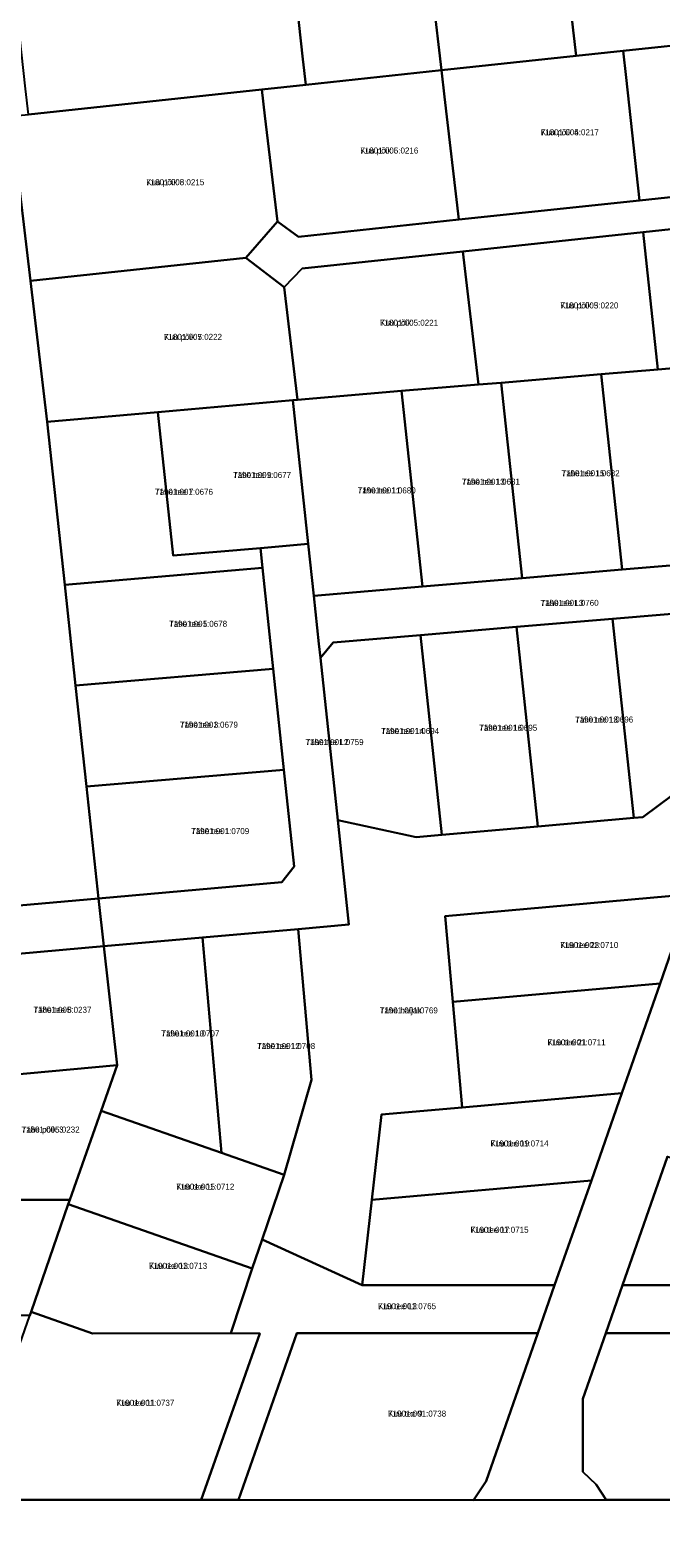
# Model space of a CAD drawing. Extents: x 529768 to 552006, y 6562269 to 6580975.
# Drawn here: x 536990.2 to 537147.7, y 6574791.4 to 6575167.4 of the extents above; entities that cross this region are included whole.
import ezdxf

# ---------------------------------------------------------------- set-up
doc = ezdxf.new("R2010")
doc.units = 0
for name, color, linetype in [('L_AADRESS', 7, 'Continuous'), ('PIIR', 7, 'Continuous'), ('TUNNUS', 7, 'Continuous')]:
    doc.layers.add(name, color=color, linetype=linetype)

msp = doc.modelspace()

# ---------------------------------------------------------------- linework, layer by layer
at = {"layer": 'PIIR'}
for points in [[(537087.57, 6575203.86), (537092.16, 6575163.84), (537092.9, 6575157.43), (537059.07, 6575153.83), (537058.36, 6575160.23), (537054.88, 6575191.53), (537061.85, 6575201.29)], [(537121.39, 6575207.24), (537122.33, 6575198.78), (537125.81, 6575167.42), (537126.53, 6575161.02), (537092.9, 6575157.43), (537092.16, 6575163.84), (537087.57, 6575203.86)], [(537122.33, 6575198.78), (537178.02, 6575204.73), (537181.66, 6575173.37), (537182.4, 6575166.98), (537138.33, 6575162.28), (537126.53, 6575161.02), (537125.81, 6575167.42)], [(536984.76, 6575192.53), (537045.52, 6575199.03), (537054.88, 6575191.53), (537058.36, 6575160.23), (537059.07, 6575153.83), (537048.08, 6575152.65), (536989.8, 6575146.44), (536989.09, 6575152.84)], [(537044.13, 6575110.65), (537051.97, 6575119.73), (537057.24, 6575115.92), (537097.3, 6575120.19), (537142.39, 6575125), (537182.73, 6575129.3), (537181.58, 6575139.24), (537185.56, 6575139.66), (537183.16, 6575160.38), (537182.4, 6575166.98), (537184.57, 6575167.21), (537193.32, 6575086.82), (537191.69, 6575086.66), (537187.63, 6575121.78), (537143.25, 6575117.05), (537098.24, 6575112.24), (537058.16, 6575107.97), (537053.62, 6575103.32)], [(537138.33, 6575162.28), (537182.4, 6575166.98), (537183.16, 6575160.38), (537185.56, 6575139.66), (537181.58, 6575139.24), (537182.73, 6575129.3), (537142.39, 6575125), (537139.05, 6575155.67)], [(537092.9, 6575157.43), (537126.53, 6575161.02), (537138.33, 6575162.28), (537139.05, 6575155.67), (537142.39, 6575125), (537097.3, 6575120.19), (537093.68, 6575150.83)], [(537048.08, 6575152.65), (537059.07, 6575153.83), (537092.9, 6575157.43), (537093.68, 6575150.83), (537097.3, 6575120.19), (537057.24, 6575115.92), (537051.97, 6575119.73), (537048.86, 6575146.05)], [(536985.5, 6575145.98), (536989.8, 6575146.44), (537048.08, 6575152.65), (537048.86, 6575146.05), (537051.97, 6575119.73), (537044.13, 6575110.65), (536990.35, 6575104.91), (536986.28, 6575139.38)], [(537007.29, 6574950.89), (536901.57, 6574941.52), (536880.9, 6575127.58), (536880.17, 6575134.18), (536908, 6575137.3), (536935.42, 6575140.37), (536985.5, 6575145.98), (536986.28, 6575139.38), (536990.35, 6575104.91), (536994.51, 6575069.75), (536998.88, 6575029.1), (537001.6, 6575003.96), (537004.29, 6574978.77)], [(537146.93, 6575082.84), (537143.25, 6575117.05), (537187.63, 6575121.78), (537191.69, 6575086.66), (537157.72, 6575083.76)], [(537107.8, 6575079.49), (537102.14, 6575079.04), (537098.24, 6575112.24), (537143.25, 6575117.05), (537146.93, 6575082.84), (537132.83, 6575081.61)], [(537022.12, 6575072.17), (536994.51, 6575069.75), (536990.35, 6575104.91), (537044.13, 6575110.65), (537053.62, 6575103.32), (537057.02, 6575075.25), (537055.85, 6575075.14)], [(537057.02, 6575075.25), (537053.62, 6575103.32), (537058.16, 6575107.97), (537098.24, 6575112.24), (537102.14, 6575079.04), (537082.94, 6575077.45)], [(537138.02, 6575032.9), (537132.83, 6575081.61), (537146.93, 6575082.84), (537157.72, 6575083.76), (537162.92, 6575034.97)], [(537113.11, 6575030.76), (537107.8, 6575079.49), (537132.83, 6575081.61), (537138.02, 6575032.9)], [(537059.69, 6575039.29), (537055.85, 6575075.14), (537057.02, 6575075.25), (537082.94, 6575077.45), (537088.17, 6575028.66), (537061.07, 6575026.35)], [(537088.17, 6575028.66), (537082.94, 6575077.45), (537102.14, 6575079.04), (537107.8, 6575079.49), (537113.11, 6575030.76)], [(536998.88, 6575029.1), (536994.51, 6575069.75), (537022.12, 6575072.17), (537025.91, 6575036.43), (537047.73, 6575038.27), (537048.27, 6575033.31)], [(537025.91, 6575036.43), (537022.12, 6575072.17), (537055.85, 6575075.14), (537059.69, 6575039.29), (537047.73, 6575038.27)], [(537048.27, 6575033.31), (537047.73, 6575038.27), (537059.69, 6575039.29), (537061.07, 6575026.35), (537062.34, 6575014.42), (537062.7, 6575010.87), (537067.05, 6574970.39), (537069.8, 6574944.41), (537057.19, 6574943.22), (537033.27, 6574941.14), (537008.67, 6574938.98), (537007.29, 6574950.89), (537053.05, 6574954.94), (537056.19, 6574958.82), (537053.6, 6574982.96), (537050.95, 6575008.17)], [(537062.34, 6575014.42), (537061.07, 6575026.35), (537088.17, 6575028.66), (537113.11, 6575030.76), (537138.02, 6575032.9), (537162.92, 6575034.97), (537184.97, 6575036.84), (537179.53, 6575021.3), (537178.5, 6575023.37), (537176.3, 6575024.05), (537135.63, 6575020.63), (537111.64, 6575018.59), (537087.73, 6575016.57), (537065.9, 6575014.72), (537062.7, 6575010.87)], [(537001.6, 6575003.96), (536998.88, 6575029.1), (537048.27, 6575033.31), (537050.95, 6575008.17)], [(537140.94, 6574970.99), (537135.63, 6575020.63), (537176.3, 6575024.05), (537178.5, 6575023.37), (537179.53, 6575021.3), (537168.6, 6574990), (537143.23, 6574971.19)], [(537116.96, 6574968.86), (537111.64, 6575018.59), (537135.63, 6575020.63), (537140.94, 6574970.99)], [(537067.05, 6574970.39), (537062.7, 6575010.87), (537065.9, 6575014.72), (537087.73, 6575016.57), (537092.99, 6574966.78), (537086.6, 6574966.17)], [(537092.99, 6574966.78), (537087.73, 6575016.57), (537111.64, 6575018.59), (537116.96, 6574968.86)], [(537004.29, 6574978.77), (537001.6, 6575003.96), (537050.95, 6575008.17), (537053.6, 6574982.96)], [(537069.8, 6574944.41), (537067.05, 6574970.39), (537086.6, 6574966.17), (537092.99, 6574966.78), (537116.96, 6574968.86), (537140.94, 6574970.99), (537143.23, 6574971.19), (537168.6, 6574990), (537155.3, 6574951.95), (537093.86, 6574946.5), (537095.75, 6574925.08), (537098.09, 6574898.78), (537077.92, 6574896.98), (537075.52, 6574875.71), (537073.12, 6574854.43), (537048.17, 6574865.82), (537053.63, 6574881.99), (537060.5, 6574905.68), (537057.19, 6574943.22)], [(537007.29, 6574950.89), (537004.29, 6574978.77), (537053.6, 6574982.96), (537056.19, 6574958.82), (537053.05, 6574954.94)], [(537095.75, 6574925.08), (537093.86, 6574946.5), (537155.3, 6574951.95), (537147.49, 6574929.7)], [(537011.93, 6574909.3), (537008.67, 6574938.98), (537033.27, 6574941.14), (537038.01, 6574887.42), (537007.96, 6574897.94)], [(537038.01, 6574887.42), (537033.27, 6574941.14), (537057.19, 6574943.22), (537060.5, 6574905.68), (537053.63, 6574881.99)], [(537008.67, 6574938.98), (537011.93, 6574909.3), (536973.07, 6574905.74), (536970.43, 6574935.57)], [(537098.09, 6574898.78), (537095.75, 6574925.08), (537147.49, 6574929.7), (537137.93, 6574902.32)], [(537011.93, 6574909.3), (537007.96, 6574897.94), (537000.17, 6574875.68), (536966.42, 6574875.68), (536973.07, 6574905.74)], [(537130.35, 6574880.54), (537075.52, 6574875.71), (537077.92, 6574896.98), (537098.09, 6574898.78), (537137.93, 6574902.32)], [(537000.17, 6574875.68), (537007.96, 6574897.94), (537038.01, 6574887.42), (537053.63, 6574881.99), (537048.17, 6574865.82), (537045.71, 6574858.56), (536999.77, 6574874.6)], [(537188.99, 6574854.44), (537138.13, 6574854.45), (537149.34, 6574886.49), (537194.64, 6574870.6)], [(537121.19, 6574854.44), (537073.12, 6574854.43), (537075.52, 6574875.71), (537130.35, 6574880.54)], [(536966.42, 6574875.68), (537000.17, 6574875.68), (536999.77, 6574874.6), (536990.46, 6574847.82), (536990.13, 6574846.87), (536956.1, 6574846.89), (536956.1, 6574867.14)], [(537005.8, 6574842.4), (536990.46, 6574847.82), (536999.77, 6574874.6), (537045.71, 6574858.56), (537040.32, 6574842.44)], [(537045.71, 6574858.56), (537048.17, 6574865.82), (537073.12, 6574854.43), (537121.19, 6574854.44), (537116.99, 6574842.47), (537056.79, 6574842.45), (537042.22, 6574800.86), (537032.98, 6574800.86), (537047.58, 6574842.41), (537040.32, 6574842.44)], [(537133.94, 6574842.42), (537138.13, 6574854.45), (537188.99, 6574854.44), (537192.79, 6574851.13), (537189.74, 6574842.43), (537185.12, 6574842.45)], [(536990.13, 6574846.87), (536990.46, 6574847.82), (537005.8, 6574842.4), (537040.32, 6574842.44), (537047.58, 6574842.41), (537032.98, 6574800.86), (536974.02, 6574800.86)], [(537042.22, 6574800.86), (537056.79, 6574842.45), (537116.99, 6574842.47), (537104.06, 6574805.54), (537100.92, 6574800.84)], [(537128.22, 6574826.08), (537133.94, 6574842.42), (537185.12, 6574842.45), (537194.81, 6574801.99), (537190.11, 6574800.87), (537134.01, 6574800.85), (537131.56, 6574804.71), (537128.22, 6574807.84)]]:
    msp.add_lwpolyline(points, close=True, dxfattribs=at)
for points in [[(537149.34, 6574886.49), (537138.13, 6574854.45), (537133.94, 6574842.42), (537128.22, 6574826.08), (537128.22, 6574807.84), (537131.56, 6574804.71), (537134.01, 6574800.85), (537100.92, 6574800.84), (537104.06, 6574805.54), (537116.99, 6574842.47), (537121.19, 6574854.44), (537130.35, 6574880.54), (537137.93, 6574902.32), (537147.49, 6574929.7), (537155.3, 6574951.95)], [(536901.57, 6574941.52), (537007.29, 6574950.89), (537008.67, 6574938.98), (536970.43, 6574935.57)], [(536967, 6574780.75), (536971.33, 6574792.88), (536974.02, 6574800.86), (537032.98, 6574800.86), (537042.22, 6574800.86), (537100.92, 6574800.84), (537134.01, 6574800.85), (537190.11, 6574800.87), (537194.81, 6574801.99), (537249.39, 6574815.06), (537304.95, 6574828.36), (537316.59, 6574831.13), (537368.37, 6574843.6), (537405.26, 6574852.44), (537416.98, 6574855.26), (537447.39, 6574862.49), (537461.1, 6574875.4)]]:
    msp.add_lwpolyline(points, dxfattribs=at)

# ---------------------------------------------------------------- texts
at = {"layer": 'L_AADRESS'}
for s, p in [('Kuu põik 4', (537117.72, 6575141.24)), ('Kuu põik 6', (537072.66, 6575136.68)), ('Kuu põik 8', (537019.22, 6575128.78)), ('Kuu põik 3', (537122.6, 6575098.04)), ('Kuu põik 5', (537077.6, 6575093.74)), ('Kuu põik 7', (537023.65, 6575090.2)), ('Tähe tee 9', (537040.9, 6575055.76)), ('Tähe tee 15', (537122.91, 6575056.19)), ('Tähe tee 11', (537072.01, 6575051.9)), ('Tähe tee 13', (537098.02, 6575054.09)), ('Tähe tee 7', (537021.39, 6575051.56)), ('Tähe tee L3', (537117.66, 6575023.86)), ('Tähe tee 5', (537024.92, 6575018.63)), ('Tähe tee 3', (537027.61, 6574993.47)), ('Tähe tee 14', (537077.85, 6574991.9)), ('Tähe tee 16', (537102.34, 6574992.7)), ('Tähe tee 18', (537126.29, 6574994.76)), ('Tähe tee L2', (537058.99, 6574989.13)), ('Tähe tee 1', (537030.44, 6574966.93)), ('Kuu tee 23', (537122.57, 6574938.51)), ('Tähe tee 8', (536991.05, 6574922.36)), ('Tähe haljak', (537077.52, 6574922.21)), ('Tähe tee 10', (537022.98, 6574916.46)), ('Tähe tee 12', (537046.89, 6574913.33)), ('Kuu tee 21', (537119.4, 6574914.24)), ('Tähe põik 3', (536988.1, 6574892.49)), ('Kuu tee 19', (537105.16, 6574889.02)), ('Kuu tee 15', (537026.72, 6574878.25)), ('Kuu tee 17', (537100.18, 6574867.49)), ('Kuu tee 13', (537019.93, 6574858.5)), ('Kuu tee L3', (537077.08, 6574848.44)), ('Kuu tee 11', (537011.74, 6574824.34)), ('Kuu tee 9', (537079.6, 6574821.65))]:
    msp.add_text(s, height=1.5, dxfattribs=at).set_placement(p)
at = {"layer": 'TUNNUS'}
for s, p in [('71801:005:0217', (537117.72, 6575141.24)), ('71801:005:0216', (537072.66, 6575136.68)), ('71801:005:0215', (537019.22, 6575128.78)), ('71801:005:0220', (537122.6, 6575098.04)), ('71801:005:0221', (537077.6, 6575093.74)), ('71801:005:0222', (537023.65, 6575090.2)), ('71901:001:0677', (537040.9, 6575055.76)), ('71901:001:0682', (537122.91, 6575056.19)), ('71901:001:0680', (537072.01, 6575051.9)), ('71901:001:0681', (537098.02, 6575054.09)), ('71901:001:0676', (537021.39, 6575051.56)), ('71901:001:0760', (537117.66, 6575023.86)), ('71901:001:0678', (537024.92, 6575018.63)), ('71901:001:0679', (537027.61, 6574993.47)), ('71901:001:0694', (537077.85, 6574991.9)), ('71901:001:0695', (537102.34, 6574992.7)), ('71901:001:0696', (537126.29, 6574994.76)), ('71901:001:0759', (537058.99, 6574989.13)), ('71901:001:0709', (537030.44, 6574966.93)), ('71901:001:0710', (537122.57, 6574938.51)), ('71801:005:0237', (536991.05, 6574922.36)), ('71901:001:0769', (537077.52, 6574922.21)), ('71901:001:0707', (537022.98, 6574916.46)), ('71901:001:0708', (537046.89, 6574913.33)), ('71901:001:0711', (537119.4, 6574914.24)), ('71801:005:0232', (536988.1, 6574892.49)), ('71901:001:0714', (537105.16, 6574889.02)), ('71901:001:0712', (537026.72, 6574878.25)), ('71901:001:0715', (537100.18, 6574867.49)), ('71901:001:0713', (537019.93, 6574858.5)), ('71901:001:0765', (537077.08, 6574848.44)), ('71901:001:0737', (537011.74, 6574824.34)), ('71901:001:0738', (537079.6, 6574821.65))]:
    msp.add_text(s, height=1.5, dxfattribs=at).set_placement(p)

doc.saveas('drawing.dxf')
